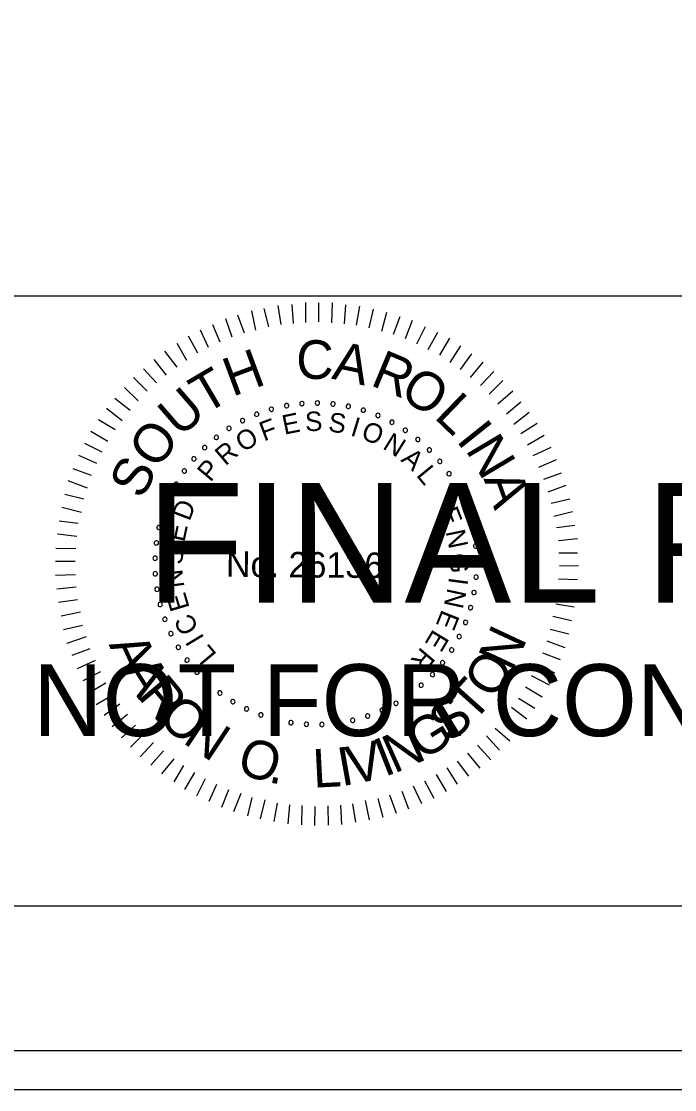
# Model space of a CAD drawing. Extents: x 967 to 1326, y 964 to 2864.
# Drawn here: x 1170.56 to 1189.3, y 1243.72 to 1274.36 of the extents above; entities that cross this region are included whole.
import ezdxf

# ---------------------------------------------------------------- set-up
doc = ezdxf.new("R2010")
doc.units = 0
for name, color, linetype in [('RD_PD_Final_TX', 7, 'Continuous'), ('RD_XS_TX_Elev_PR', 7, 'Continuous'), ('RD_XS_TX_Misc', 7, 'Continuous'), ('RD_XS_TX_ShdSlope', 7, 'Continuous')]:
    doc.layers.add(name, color=color, linetype=linetype)

msp = doc.modelspace()

# ---------------------------------------------------------------- linework, layer by layer
at = {"layer": 'RD_PD_Final_TX'}
for p, q in [((996.114, 1266.486), (1323.886, 1266.486)), ((1323.886, 1248.983), (996.114, 1248.983))]:
    msp.add_line(p, q, dxfattribs=at)
at = {"layer": 'RD_XS_TX_Elev_PR'}
for points in [[(967.409, 1243.72), (1326.285, 1243.72), (1326.285, 1463.72), (967.409, 1463.72)], [(988.525, 1244.84), (1326.285, 1244.84), (1326.285, 1462.6), (988.525, 1462.6)]]:
    msp.add_lwpolyline(points, close=True, dxfattribs=at)
at = {"layer": 'RD_XS_TX_ShdSlope'}
for p, q in [((1177.287, 1265.508), (1177.169, 1266.054)), ((1177.657, 1265.597), (1177.53, 1266.128)), ((1178.01, 1265.663), (1177.93, 1266.209)), ((1178.364, 1265.699), (1178.33, 1266.244)), ((1178.717, 1265.719), (1178.722, 1266.295)), ((1179.093, 1265.739), (1179.098, 1266.292)), ((1179.469, 1265.713), (1179.489, 1266.288)), ((1179.829, 1265.687), (1179.872, 1266.231)), ((1180.174, 1265.646), (1180.271, 1266.19)), ((1180.535, 1265.573), (1180.662, 1266.102)), ((1176.61, 1265.306), (1176.423, 1265.83)), ((1176.964, 1265.419), (1176.769, 1265.935)), ((1180.902, 1265.478), (1181.045, 1266.022)), ((1181.231, 1265.384), (1181.428, 1265.896)), ((1181.584, 1265.265), (1181.78, 1265.786)), ((1175.933, 1265.005), (1175.699, 1265.506)), ((1176.264, 1265.156), (1176.053, 1265.657)), ((1181.905, 1265.109), (1182.154, 1265.606)), ((1182.226, 1264.953), (1182.506, 1265.45)), ((1175.308, 1264.634), (1175.036, 1265.12)), ((1175.624, 1264.846), (1175.352, 1265.332)), ((1182.562, 1264.789), (1182.85, 1265.27)), ((1175.03, 1264.445), (1174.681, 1264.9)), ((1182.86, 1264.572), (1183.163, 1265.053)), ((1183.158, 1264.378), (1183.484, 1264.828)), ((1174.729, 1264.217), (1174.372, 1264.665)), ((1183.447, 1264.145), (1183.811, 1264.587)), ((1174.435, 1263.997), (1174.062, 1264.399)), ((1183.729, 1263.92), (1184.116, 1264.316)), ((1174.172, 1263.753), (1173.776, 1264.148)), ((1183.98, 1263.672), (1184.368, 1264.061)), ((1173.909, 1263.479), (1173.52, 1263.858)), ((1184.232, 1263.394), (1184.657, 1263.767)), ((1173.684, 1263.197), (1173.242, 1263.546)), ((1184.475, 1263.108), (1184.892, 1263.45)), ((1173.451, 1262.9), (1173.009, 1263.256)), ((1184.687, 1262.807), (1185.128, 1263.156)), ((1173.257, 1262.64), (1172.776, 1262.936)), ((1184.885, 1262.544), (1185.355, 1262.832)), ((1173.039, 1262.312), (1172.559, 1262.6)), ((1185.081, 1262.213), (1185.56, 1262.493)), ((1172.883, 1262.006), (1172.379, 1262.256)), ((1185.24, 1261.904), (1185.756, 1262.145)), ((1172.727, 1261.677), (1172.215, 1261.904)), ((1185.399, 1261.573), (1185.907, 1261.791)), ((1172.571, 1261.333), (1172.051, 1261.53)), ((1172.461, 1260.974), (1171.91, 1261.178)), ((1185.549, 1261.226), (1186.057, 1261.414)), ((1185.669, 1260.865), (1186.185, 1261.06)), ((1172.351, 1260.652), (1171.807, 1260.787)), ((1185.759, 1260.541), (1186.297, 1260.667)), ((1172.286, 1260.276), (1171.727, 1260.419)), ((1185.832, 1260.165), (1186.371, 1260.298)), ((1172.191, 1259.955), (1171.647, 1260.029)), ((1172.15, 1259.587), (1171.598, 1259.653)), ((1185.906, 1259.842), (1186.436, 1259.906)), ((1185.964, 1259.473), (1186.51, 1259.53)), ((1172.124, 1259.234), (1171.548, 1259.239)), ((1185.977, 1259.12), (1186.514, 1259.115)), ((1172.105, 1258.866), (1171.545, 1258.871)), ((1185.997, 1258.751), (1186.542, 1258.747)), ((1172.118, 1258.482), (1171.542, 1258.471)), ((1172.138, 1258.136), (1171.585, 1258.072)), ((1185.971, 1258.368), (1186.508, 1258.348)), ((1172.173, 1257.768), (1171.627, 1257.688)), ((1185.952, 1258.022), (1186.497, 1257.949)), ((1185.888, 1257.655), (1186.417, 1257.566)), ((1172.262, 1257.414), (1171.701, 1257.296)), ((1185.808, 1257.302), (1186.345, 1257.175)), ((1172.321, 1257.037), (1171.774, 1256.911)), ((1185.729, 1256.926), (1186.265, 1256.792)), ((1172.425, 1256.707), (1171.871, 1256.519)), ((1185.634, 1256.597), (1186.146, 1256.401)), ((1172.53, 1256.36), (1172.007, 1256.173)), ((1185.508, 1256.253), (1186.013, 1256.057)), ((1172.681, 1256.029), (1172.165, 1255.788)), ((1185.352, 1255.924), (1185.857, 1255.675)), ((1172.831, 1255.705), (1172.323, 1255.441)), ((1172.982, 1255.374), (1172.497, 1255.094)), ((1185.188, 1255.603), (1185.7, 1255.33)), ((1173.194, 1255.042), (1172.709, 1254.762)), ((1185.024, 1255.274), (1185.498, 1254.987)), ((1173.384, 1254.78), (1172.936, 1254.453)), ((1184.822, 1254.946), (1185.288, 1254.658)), ((1173.612, 1254.478), (1173.164, 1254.129)), ((1184.62, 1254.687), (1185.055, 1254.353)), ((1173.832, 1254.177), (1173.437, 1253.812)), ((1184.155, 1254.092), (1184.574, 1253.72)), ((1184.403, 1254.389), (1184.814, 1254.033)), ((1174.091, 1253.945), (1173.689, 1253.541)), ((1183.899, 1253.864), (1184.28, 1253.454)), ((1174.35, 1253.674), (1173.97, 1253.263)), ((1183.644, 1253.597), (1184.024, 1253.18)), ((1174.64, 1253.442), (1174.275, 1253.022)), ((1174.937, 1253.209), (1174.58, 1252.782)), ((1183.358, 1253.37), (1183.715, 1252.944)), ((1175.212, 1253.014), (1174.932, 1252.549)), ((1182.764, 1252.952), (1183.059, 1252.482)), ((1183.065, 1253.141), (1183.384, 1252.709)), ((1175.525, 1252.812), (1175.245, 1252.331)), ((1175.83, 1252.633), (1175.588, 1252.136)), ((1182.124, 1252.581), (1182.396, 1252.08)), ((1182.463, 1252.755), (1182.743, 1252.269)), ((1176.159, 1252.477), (1175.94, 1251.98)), ((1176.503, 1252.321), (1176.307, 1251.816)), ((1181.476, 1252.28), (1181.664, 1251.771)), ((1181.8, 1252.431), (1182.041, 1251.93)), ((1176.855, 1252.211), (1176.651, 1251.69)), ((1177.177, 1252.1), (1177.05, 1251.572)), ((1177.545, 1252.036), (1177.409, 1251.484)), ((1180.423, 1252.012), (1180.541, 1251.458)), ((1180.791, 1252.07), (1180.926, 1251.54)), ((1181.122, 1252.175), (1181.31, 1251.652)), ((1177.897, 1251.933), (1177.808, 1251.412)), ((1178.25, 1251.892), (1178.207, 1251.34)), ((1178.603, 1251.866), (1178.598, 1251.313)), ((1178.978, 1251.84), (1178.974, 1251.295)), ((1179.355, 1251.86), (1179.365, 1251.307)), ((1179.715, 1251.88), (1179.749, 1251.327)), ((1180.061, 1251.915), (1180.149, 1251.393))]:
    msp.add_line(p, q, dxfattribs=at)
for centre, start, end in [((1177.734, 1263.235), 16.1422, 196.1422), ((1178.168, 1263.337), 10.6038, 190.6038), ((1178.168, 1263.337), 190.6038, 10.6038), ((1178.609, 1263.397), 5.0653, 185.0653), ((1178.609, 1263.397), 185.0653, 5.0653), ((1179.055, 1263.414), 359.5268, 179.5268), ((1179.055, 1263.414), 179.5268, 359.5268), ((1179.5, 1263.388), 353.9884, 173.9884), ((1179.5, 1263.388), 173.9884, 353.9884), ((1179.94, 1263.319), 168.4499, 348.4499), ((1179.94, 1263.319), 348.4499, 168.4499), ((1177.312, 1263.091), 21.6807, 201.6807), ((1177.312, 1263.091), 201.6807, 21.6807), ((1177.734, 1263.235), 196.1422, 16.1422), ((1180.372, 1263.208), 162.9114, 342.9114), ((1180.372, 1263.208), 342.9114, 162.9114), ((1180.79, 1263.056), 157.373, 337.373), ((1180.79, 1263.056), 337.373, 157.373), ((1176.52, 1262.686), 32.7576, 212.7576), ((1176.52, 1262.686), 212.7576, 32.7576), ((1176.906, 1262.908), 27.2191, 207.2191), ((1176.906, 1262.908), 207.2191, 27.2191), ((1181.193, 1262.864), 151.8345, 331.8345), ((1181.193, 1262.864), 331.8345, 151.8345), ((1181.574, 1262.634), 146.2961, 326.2961), ((1181.574, 1262.634), 326.2961, 146.2961), ((1176.156, 1262.428), 38.2961, 218.2961), ((1176.156, 1262.428), 218.2961, 38.2961), ((1181.932, 1262.368), 140.7576, 320.7576), ((1181.932, 1262.368), 320.7576, 140.7576), ((1175.82, 1262.135), 43.8345, 223.8345), ((1175.82, 1262.135), 223.8345, 43.8345), ((1182.263, 1262.069), 135.2191, 315.2191), ((1182.263, 1262.069), 315.2191, 135.2191), ((1175.513, 1261.812), 49.373, 229.373), ((1175.513, 1261.812), 229.373, 49.373), ((1182.563, 1261.74), 129.6807, 309.6807), ((1182.563, 1261.74), 309.6807, 129.6807), ((1175.239, 1261.461), 54.9114, 234.9114), ((1175.239, 1261.461), 234.9114, 54.9114), ((1182.83, 1261.383), 304.1422, 124.1422), ((1175, 1261.085), 60.4499, 240.4499), ((1175, 1261.085), 240.4499, 60.4499), ((1182.83, 1261.383), 124.1422, 304.1422), ((1183.061, 1261.002), 118.6038, 298.6038), ((1183.061, 1261.002), 298.6038, 118.6038), ((1174.798, 1260.687), 65.9884, 245.9884), ((1174.798, 1260.687), 245.9884, 65.9884), ((1183.255, 1260.601), 113.0653, 293.0653), ((1183.255, 1260.601), 293.0653, 113.0653), ((1174.636, 1260.272), 71.5268, 251.5268), ((1174.636, 1260.272), 251.5268, 71.5268), ((1183.408, 1260.182), 107.5268, 287.5268), ((1183.408, 1260.182), 287.5268, 107.5268), ((1174.514, 1259.843), 77.0653, 257.0653), ((1174.514, 1259.843), 257.0653, 77.0653), ((1183.521, 1259.751), 101.9884, 281.9884), ((1183.521, 1259.751), 281.9884, 101.9884), ((1174.435, 1259.405), 82.6038, 262.6038), ((1174.435, 1259.405), 262.6038, 82.6038), ((1183.592, 1259.311), 96.4499, 276.4499), ((1183.592, 1259.311), 276.4499, 96.4499), ((1174.398, 1258.961), 88.1422, 268.1422), ((1174.398, 1258.961), 268.1422, 88.1422), ((1183.619, 1258.866), 90.9114, 270.9114), ((1183.619, 1258.866), 270.9114, 90.9114), ((1174.404, 1258.515), 93.6807, 273.6807), ((1174.404, 1258.515), 273.6807, 93.6807), ((1183.604, 1258.421), 85.373, 265.373), ((1183.604, 1258.421), 265.373, 85.373), ((1174.453, 1258.072), 99.2191, 279.2191), ((1174.453, 1258.072), 279.2191, 99.2191), ((1183.546, 1257.979), 79.8345, 259.8345), ((1183.546, 1257.979), 259.8345, 79.8345), ((1174.545, 1257.636), 104.7576, 284.7576), ((1174.545, 1257.636), 284.7576, 104.7576), ((1183.445, 1257.545), 74.2961, 254.2961), ((1183.445, 1257.545), 254.2961, 74.2961), ((1174.678, 1257.211), 110.2961, 290.2961), ((1174.678, 1257.211), 290.2961, 110.2961), ((1183.303, 1257.122), 68.7576, 248.7576), ((1183.303, 1257.122), 248.7576, 68.7576), ((1174.852, 1256.8), 115.8345, 295.8345), ((1174.852, 1256.8), 295.8345, 115.8345), ((1183.121, 1256.716), 63.2191, 243.2191), ((1183.121, 1256.716), 243.2191, 63.2191), ((1175.065, 1256.409), 121.373, 301.373), ((1175.065, 1256.409), 301.373, 121.373), ((1182.9, 1256.328), 57.6807, 237.6807), ((1182.9, 1256.328), 237.6807, 57.6807), ((1175.314, 1256.039), 126.9114, 306.9114), ((1175.314, 1256.039), 306.9114, 126.9114), ((1182.643, 1255.964), 52.1422, 232.1422), ((1182.643, 1255.964), 232.1422, 52.1422), ((1175.598, 1255.696), 132.4499, 312.4499), ((1175.598, 1255.696), 312.4499, 132.4499), ((1182.353, 1255.627), 46.6038, 226.6038), ((1182.353, 1255.627), 226.6038, 46.6038), ((1175.914, 1255.381), 137.9884, 317.9884), ((1175.914, 1255.381), 317.9884, 137.9884), ((1182.03, 1255.319), 41.0653, 221.0653), ((1182.03, 1255.319), 221.0653, 41.0653), ((1176.258, 1255.099), 143.5268, 323.5268), ((1176.258, 1255.099), 323.5268, 143.5268), ((1181.68, 1255.043), 35.5268, 215.5268), ((1181.68, 1255.043), 215.5268, 35.5268), ((1176.629, 1254.851), 149.0653, 329.0653), ((1176.629, 1254.851), 329.0653, 149.0653), ((1177.021, 1254.639), 334.6038, 154.6038), ((1181.305, 1254.803), 29.9884, 209.9884), ((1181.305, 1254.803), 209.9884, 29.9884), ((1177.021, 1254.639), 154.6038, 334.6038), ((1177.432, 1254.467), 160.1422, 340.1422), ((1177.432, 1254.467), 340.1422, 160.1422), ((1177.858, 1254.335), 345.6807, 165.6807), ((1180.494, 1254.436), 18.9114, 198.9114), ((1180.494, 1254.436), 198.9114, 18.9114), ((1180.908, 1254.6), 24.4499, 204.4499), ((1180.908, 1254.6), 204.4499, 24.4499), ((1177.858, 1254.335), 165.6807, 345.6807), ((1178.294, 1254.245), 351.2191, 171.2191), ((1178.294, 1254.245), 171.2191, 351.2191), ((1178.737, 1254.198), 356.7576, 176.7576), ((1178.737, 1254.198), 176.7576, 356.7576), ((1179.183, 1254.193), 2.2961, 182.2961), ((1179.183, 1254.193), 182.2961, 2.2961), ((1179.627, 1254.232), 7.8345, 187.8345), ((1179.627, 1254.232), 187.8345, 7.8345), ((1180.065, 1254.313), 13.373, 193.373), ((1180.065, 1254.313), 193.373, 13.373)]:
    msp.add_arc(centre, 0.0627, start, end, dxfattribs=at)

# ---------------------------------------------------------------- texts
at = {"layer": 'RD_XS_TX_Misc'}
for s, height, p in [('FINAL PLANS', 3.4375, (1174.145, 1257.685)), ('NOT FOR CONSTRUCTION', 2.0625, (1170.901, 1253.86))]:
    msp.add_text(s, height=height, dxfattribs=at).set_placement(p)
at = {"layer": 'RD_XS_TX_ShdSlope'}
for s, height, rotation, p in [('C', 1.11, 359.5482, (1178.442, 1264.108)), ('H', 1.11, 20.3637, (1176.614, 1263.587)), ('A', 1.11, 348.1981, (1179.439, 1264.115)), ('R', 1.11, 337.4344, (1180.541, 1263.937)), ('T', 1.11, 30.4992, (1175.828, 1263.072)), ('O', 1.108, 326.5869, (1181.366, 1263.609)), ('U', 1.11, 40.8022, (1175.102, 1262.403)), ('L', 1.11, 315.9488, (1182.373, 1263.003)), ('F', 0.557, 20.6127, (1177.52, 1262.309)), ('E', 0.557, 11.4103, (1178.103, 1262.503)), ('S', 0.557, 2.208, (1178.709, 1262.601)), ('S', 0.557, 352.6608, (1179.346, 1262.599)), ('I', 0.557, 343.1136, (1179.975, 1262.491)), ('O', 1.11, 52.0267, (1174.435, 1261.474)), ('O', 0.557, 338.4392, (1180.274, 1262.401)), ('I', 1.11, 308.6613, (1183.011, 1262.338)), ('O', 0.557, 30.8477, (1176.917, 1261.987)), ('N', 0.557, 328.2042, (1180.896, 1262.12)), ('N', 1.11, 300.7037, (1183.285, 1262.075)), ('R', 0.557, 40.3949, (1176.415, 1261.594)), ('S', 1.108, 63.2511, (1174.029, 1260.619)), ('P', 0.557, 49.9421, (1175.985, 1261.124)), ('A', 0.557, 318.657, (1181.424, 1261.762)), ('L', 0.557, 309.4546, (1181.869, 1261.339)), ('A', 1.11, 289.4792, (1183.814, 1261.243)), ('D', 0.557, 69.0364, (1175.386, 1260.003)), ('E', 0.557, 291.049, (1182.53, 1260.307)), ('E', 0.557, 78.2388, (1175.238, 1259.407)), ('N', 0.557, 281.8466, (1182.728, 1259.726)), ('S', 0.557, 87.786, (1175.187, 1258.772)), ('No. 26136', 0.7311, 359.5268, (1176.429, 1258.43)), ('G', 0.557, 272.2995, (1182.833, 1259.097)), ('N', 0.557, 97.3332, (1175.242, 1258.137)), ('I', 0.557, 262.4084, (1182.83, 1258.437)), ('E', 0.557, 106.5355, (1175.394, 1257.541)), ('N', 0.557, 257.7339, (1182.789, 1258.127)), ('C', 0.557, 116.4266, (1175.661, 1256.938)), ('E', 0.557, 248.1867, (1182.628, 1257.511)), ('E', 0.557, 238.9844, (1182.378, 1256.949)), ('N', 1.105, 64.8922, (1184.632, 1255.684)), ('A', 1.105, 294.7297, (1173.062, 1256.486)), ('I', 0.557, 121.1011, (1175.823, 1256.67)), ('L', 0.557, 129.9595, (1176.187, 1256.204)), ('R', 0.557, 229.782, (1182.041, 1256.435)), ('A', 1.105, 302.2892, (1173.414, 1255.72)), ('O', 1.105, 56.2059, (1184.102, 1254.874)), ('R', 1.105, 309.8487, (1173.865, 1255.007)), ('T', 1.105, 48.2685, (1183.515, 1254.211)), ('O', 1.105, 317.7861, (1174.434, 1254.33)), ('S', 1.105, 40.3311, (1182.842, 1253.636)), ('N', 1.105, 326.4725, (1175.158, 1253.686)), ('G', 1.105, 32.0198, (1182.059, 1253.14)), ('N', 1.105, 24.0824, (1181.252, 1252.776)), ('O', 1.105, 342.3472, (1176.697, 1252.82)), ('I', 1.105, 21.4605, (1180.976, 1252.681)), ('L', 1.105, 2.9677, (1178.943, 1252.379)), ('I', 1.105, 10.1523, (1179.743, 1252.418)), ('V', 1.105, 12.7741, (1180.033, 1252.457)), ('.', 1.105, 351.0336, (1177.623, 1252.536))]:
    msp.add_text(s, height=height, rotation=rotation, dxfattribs=at).set_placement(p)

doc.saveas('drawing.dxf')
